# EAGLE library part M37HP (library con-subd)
SUB-D
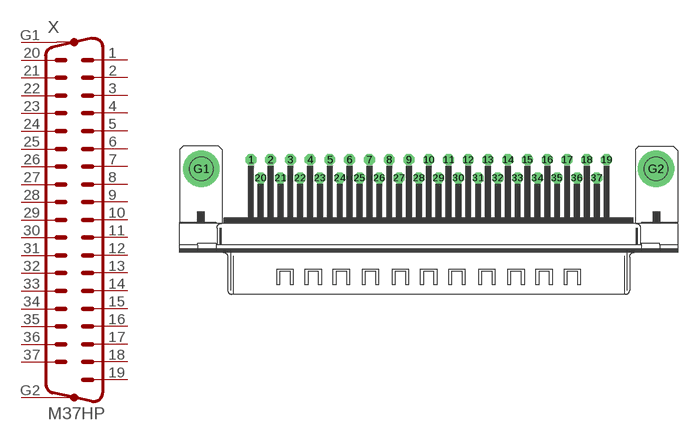
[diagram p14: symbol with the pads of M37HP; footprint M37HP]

Designator prefix X

## M37HP (OC_FARNELL: unknown; OC_NEWARK: unknown)  [M37HP]
1  1  pas
2  2  pas
3  3  pas
4  4  pas
5  5  pas
6  6  pas
7  7  pas
8  8  pas
9  9  pas
10  10  pas
11  11  pas
12  12  pas
13  13  pas
14  14  pas
15  15  pas
16  16  pas
17  17  pas
18  18  pas
19  19  pas
20  20  pas
21  21  pas
22  22  pas
23  23  pas
24  24  pas
25  25  pas
26  26  pas
27  27  pas
28  28  pas
29  29  pas
30  30  pas
31  31  pas
32  32  pas
33  33  pas
34  34  pas
35  35  pas
36  36  pas
37  37  pas
G1  G1  pas
G2  G2  pas

## Footprint M37HP (pad centres in mm)
SUB-D
drill 1.016 octagon: 1 -24.841,1.27; 2 -22.098,1.27; 3 -19.329,1.27; 4 -16.561,1.27; 5 -13.818,1.27; 6 -11.049,1.27; 7 -8.28,1.27; 8 -5.512,1.27; 9 -2.769,1.27; 10 0,1.27; 11 2.769,1.27; 12 5.512,1.27; 13 8.28,1.27; 14 11.049,1.27; 15 13.792,1.27; 16 16.561,1.27; 17 19.329,1.27; 18 22.073,1.27; 19 24.841,1.27; 20 -23.47,-1.27; 21 -20.701,-1.27; 22 -17.958,-1.27; 23 -15.189,-1.27; 24 -12.421,-1.27; 25 -9.652,-1.27; 26 -6.909,-1.27; 27 -4.14,-1.27; 28 -1.372,-1.27; 29 1.372,-1.27; 30 4.14,-1.27; 31 6.909,-1.27; 32 9.652,-1.27; 33 12.421,-1.27; 34 15.189,-1.27; 35 17.932,-1.27; 36 20.701,-1.27; 37 23.47,-1.27
drill 3.302 pad 5.08 round: G1 -31.75,0; G2 31.75,0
